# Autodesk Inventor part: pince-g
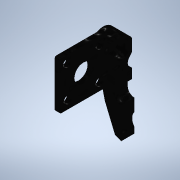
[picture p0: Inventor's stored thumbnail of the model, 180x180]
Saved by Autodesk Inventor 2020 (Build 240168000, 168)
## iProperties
Created: 2023-10
Part Number: pince-g
Material: Générique
Document SubType Name: Modeling
Designer: bruno
Density: 1 g/cm^3
Appearance: Noir
Mass: 5.45581 g
Surface Area: 42.901 cm^2
Volume: 5.45581 cm^3
Author: bruno
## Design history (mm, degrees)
sketch "Esquisse1"
  geometry: L1 (-5.917, 4)-(-43.5, 4); L2 (-43.5, 4)-(-43.5, -4); L3 (-43.5, -4)-(-5.917, -4); L4 (-5.917, -4)-(-5.917, 4); C1 r 5 at (0, 0); C2 r 7.5 at (0, 0); 3 further points
  constraints: 8 end point, 2 centre point, 2 coincident, 2 parallel, 1 horizontal, 1 perpendicular
  dimensions: "d0" = 10 diameter of C1; "d1" = 15 diameter of C2; "d2" = 4 distance from line of L3 point (0, 0); "d3" = 4 distance from line of L1 point (0, 0); "d4" = 43.5 distance from line of L2 point (0, 0)
extrude "Extrusion1" new body sketch "Esquisse1" distance "d5" = 15; taper "d6" = 0 deg
sketch "Esquisse2"
  geometry: L1 (15, 37.156)-(15, 0) reference; L2 (0, 0)-(15, 0) reference; L3 (0, 37.156)-(0, 0) reference; L4 (23.715, 19)-(11, 19); L5 (11, 19)-(11, 53.427); L6 (11, 53.427)-(23.715, 53.427); L7 (23.715, 53.427)-(23.715, 19); L8 (15, 0)-(15, 37.156) reference; L9 (15, 0)-(11.265, 1.431); L10 (0, 0)-(0, 37.156) reference; L11 (0, 37.156)-(5.093, 16.193); L12 (5.093, 16.193)-(11.265, 1.431); C1 r 6.035 at (19.697, 7.524); 1 further point
  constraints: 14 end point, 2 parallel, 1 centre point, 1 horizontal, 1 perpendicular
  dimensions: "d7" = 4 distance between parallel lines of L5 L1; "d8" = 19 distance from line of L1.end L4; "d11" = 16 distance of L11.end L9.end; "d12" = 4 distance of L1.end L9.end
extrude "Extrusion2" cut sketch "Esquisse2" stored distance "d9" = 29; taper "d10" = 0 deg
fillet "Congé1" dims "d13" = 4
fillet "Congé2" dims "d14" = 4
sketch "Esquisse3"
  geometry: L1 (6.5, 12.558)-(19.872, 12.558); L2 (19.872, 12.558)-(19.872, -11.726); L3 (19.872, -11.726)-(6.5, -11.726); L4 (6.5, -11.726)-(6.5, 12.558); 1 further point
  constraints: 8 end point, 2 parallel, 1 horizontal, 1 perpendicular
  dimensions: "d45" = 6.5 distance from line of L4 point (0, 0)
extrude "Extrusion3" cut sketch "Esquisse3" distance "d16" = 20; taper "d17" = 0 deg
sketch "Esquisse4"
  geometry: L1 (-5.713, 5.5)-(12.395, 5.5); L2 (0, 0)-(0, 12.239) reference; L3 (0, 8.5)-(0.406, 8.5); L4 (0.406, 2.5)-(0, 2.5); L5 (8, 12.239)-(8, 0) reference; L6 (7.381, 8.5)-(10.512, 8.5); L7 (10.512, 8.5)-(10.512, 2.5); L8 (10.512, 2.5)-(7.381, 2.5); L9 (7.381, 2.5)-(7.381, 8.5); 5 further points
  constraints: 14 end point, 3 horizontal, 3 parallel, 2 point on line, 1 perpendicular
  dimensions: "d18" = 15 distance from line of L1 point (4, 20.5); "d20" = 3 distance from line of L1 L3.start; "d30" = 3 distance between parallel lines of L1 L4
extrude "Extrusion4" join sketch "Esquisse4" stored distance "d22" = 20; taper "d23" = 0 deg
fillet "Congé3" dims "d24" = 4
sketch "Esquisse5"
  geometry: L1 (-8.168, 0)-(-9.626, 6) reference; L2 (0, 0)-(-8.168, 0) reference; L3 (0, 6)-(0, 0) reference; L4 (0, 6)-(-9.626, 6) reference; L5 (0, 3)-(-8.897, 3); L6 (-5.907, -9.307)-(-10.534, 9.739) reference; C1 r 1.5 at (-6.021, 3); 1 further point
  constraints: 2 end point, 2 point on line, 1 centre point, 1 horizontal, 1 midpoint
  dimensions: "d25" = 3 diameter of C1
extrude "Extrusion5" cut sketch "Esquisse5" distance "d26" = 100; taper "d27" = 0 deg
sketch "Esquisse10"
  geometry: C1 r 1.5 at (-14.718, 20.976) reference; 1 further point
extrude "Extrusion10" join sketch "Esquisse10" distance "d46" = 1; taper "d47" = 0 deg
feature "Filetage2" dims "d48" = 9.512, "d49" = 0
sketch "Esquisse11"
  geometry: L1 (-32.5, 35)-(-5.5, 35); L2 (-4.5, 34)-(-4.5, 7); L3 (-5.5, 6)-(-32.5, 6); L4 (-33.5, 7)-(-33.5, 34); L5 (4, 28)-(-4.5, 28); L6 (-1.217, 15.112)-(-4.5, 15.112); C1 r 5.5 at (-19, 20.5); C2 r 2.5 at (-9, 30.12); C3 r 2.5 at (-9.1, 10.6); C4 r 2.5 at (-28.9, 30.4); C5 r 2.5 at (-28.5, 11); A1 r 7.5 centre (4, 20.5) between (10.5, 24.242) and (-1.217, 15.112) reference; A2 r 4 centre (-4, 12.239) between (0, 12.239) and (-1.217, 15.112) reference; A3 r 1 centre (-5.5, 34) between (-4.5, 34) and (-5.5, 35); A4 r 1 centre (-32.5, 34) between (-32.5, 35) and (-33.5, 34); A5 r 1 centre (-32.5, 7) between (-33.5, 7) and (-32.5, 6); A6 r 1 centre (-5.5, 7) between (-5.5, 6) and (-4.5, 7); 1 further point
  constraints: 12 end point, 9 centre point, 9 point on circle, 9 tangent, 3 equal radius, 3 perpendicular, 2 parallel, 2 point on line, 1 horizontal
  dimensions: "d50" = 11 diameter of C1; "d51" = 14.5 distance from line of L4 C1.centre; "d52" = 23 distance of point (4, 20.5) C1.centre; "d53" = 14.5 distance from line of L2 C1.centre; "d54" = 14.5 distance from line of L1 C1.centre; "d55" = 14.5 distance from line of L3 C1.centre; "d56" = 5 diameter of C2; "d57" = 4.5 distance from line of L2 C2.centre; "d58" = 1 radius of A3; "d59" = 5 diameter of C3; "d60" = 4.6 distance from line of L2 C3.centre; "d61" = 4.6 distance from line of C3.centre L3; "d62" = 5 diameter of C4; "d63" = 4.6 distance from line of L4 C4.centre; "d64" = 5 diameter of C5; "d69" = 4.6 distance from line of L1 C4.centre
extrude "Extrusion11" join sketch "Esquisse11" distance "d65" = 3; taper "d66" = 0 deg
fillet "Congé4" dims "d67" = 2
fillet "Congé5" dims "d68" = 2
node "Solide1"
node "Boucle projetée1"
